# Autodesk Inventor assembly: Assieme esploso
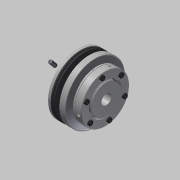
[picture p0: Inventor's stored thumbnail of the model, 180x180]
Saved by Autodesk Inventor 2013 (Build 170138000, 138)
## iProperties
Created: 2013-06
Part Number: Assieme esploso
Document SubType Name: Assembly
Designer: amir.elmekauy
Author: amir.elmekauy
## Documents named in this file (10)
- C:\Users\amir.elmekauy\Desktop\Disegni 3D\LIMITATORI\LC 170-2\Assieme chiuso.iam
- C:\Users\amir.elmekauy\Desktop\Disegni 3D\LIMITATORI\LC 170-2\Anello frizione.ipt
- C:\Users\amir.elmekauy\Desktop\Disegni 3D\LIMITATORI\LC 170-2\Bussola guida.ipt
- C:\Users\amir.elmekauy\Desktop\Disegni 3D\LIMITATORI\LC 170-2\DIN 912 - M8 x 16.ipt
- C:\Users\amir.elmekauy\Desktop\Disegni 3D\LIMITATORI\LC 170-2\Ghiera di serraggio.ipt
- C:\Users\amir.elmekauy\Desktop\Disegni 3D\LIMITATORI\LC 170-2\Molla.ipt
- C:\Users\amir.elmekauy\Desktop\Disegni 3D\LIMITATORI\LC 170-2\Mozzo.ipt
- C:\Users\amir.elmekauy\Desktop\Disegni 3D\LIMITATORI\LC 170-2\Rondella ad asola.ipt
- C:\Users\amir.elmekauy\Desktop\Disegni 3D\LIMITATORI\LC 170-2\Rondella di spinta.ipt
- C:\Users\amir.elmekauy\Desktop\Disegni 3D\LIMITATORI\LC 170-2\Grano - M10 x 25.ipt
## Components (16 placed, 9 different names)
1. Anello frizione:1 — Coincidente:1, Coincidente:18
2. Bussola guida:1 — Coincidente:3, Coincidente:19, Coincidente:20
3. DIN 912 - sostituito da DIN EN ISO 4762 M8 x 16:1 — Coincidente:12, Coincidente:21
4. Ghiera di serraggio:1 — Coincidente:4, Coincidente:12, Coincidente:13, Coincidente:14, Coincidente:15, Coincidente:16, Coincidente:17
5. Molla:1 — Coincidente:5
6. Mozzo:1 — Coincidente:6, Coincidente:9, Coincidente:11, Coincidente:18, Coincidente:19, Coincidente:27, Coincidente:28
7. Rondella ad asola:1 — Coincidente:7, Coincidente:9, Coincidente:20
8. Rondella di spinta:1 — Coincidente:10, Coincidente:11, Coincidente:21, Coincidente:22, Coincidente:23, Coincidente:24, Coincidente:25, Coincidente:26
9. Anello frizione:2 — Coincidente:2
10. DIN 912 - sostituito da DIN EN ISO 4762 M8 x 16:2 — Coincidente:13, Coincidente:22
11. DIN 912 - sostituito da DIN EN ISO 4762 M8 x 16:3 — Coincidente:16, Coincidente:26
12. DIN 912 - sostituito da DIN EN ISO 4762 M8 x 16:4 — Coincidente:17, Coincidente:25
13. DIN 912 - sostituito da DIN EN ISO 4762 M8 x 16:5 — Coincidente:15, Coincidente:24
14. DIN 912 - sostituito da DIN EN ISO 4762 M8 x 16:6 — Coincidente:14, Coincidente:23
15. DIN 913 M10 x 25:1 — Coincidente:27
16. DIN 913 M10 x 25:2 — Coincidente:28
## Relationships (27: Mate 27)
- Coincidente:1 [Mate]: Anello frizione:1
- Coincidente:2 [Mate]: Anello frizione:2
- Coincidente:3 [Mate]: Bussola guida:1
- Coincidente:4 [Mate]: Ghiera di serraggio:1
- Coincidente:5 [Mate]: Molla:1
- Coincidente:6 [Mate]: Mozzo:1
- Coincidente:7 [Mate]: Rondella ad asola:1
- Coincidente:9 [Mate]: Mozzo:1 ↔ Rondella ad asola:1
- Coincidente:10 [Mate]: Rondella di spinta:1
- Coincidente:11 [Mate]: Mozzo:1 ↔ Rondella di spinta:1
- Coincidente:12 [Mate]: DIN 912 - sostituito da DIN EN ISO 4762 M8 x 16:1 ↔ Ghiera di serraggio:1
- Coincidente:13 [Mate]: Ghiera di serraggio:1 ↔ DIN 912 - sostituito da DIN EN ISO 4762 M8 x 16:2
- Coincidente:14 [Mate]: Ghiera di serraggio:1 ↔ DIN 912 - sostituito da DIN EN ISO 4762 M8 x 16:6
- Coincidente:15 [Mate]: Ghiera di serraggio:1 ↔ DIN 912 - sostituito da DIN EN ISO 4762 M8 x 16:5
- Coincidente:16 [Mate]: Ghiera di serraggio:1 ↔ DIN 912 - sostituito da DIN EN ISO 4762 M8 x 16:3
- Coincidente:17 [Mate]: Ghiera di serraggio:1 ↔ DIN 912 - sostituito da DIN EN ISO 4762 M8 x 16:4
- Coincidente:18 [Mate]: Anello frizione:1 ↔ Mozzo:1
- Coincidente:19 [Mate]: Bussola guida:1 ↔ Mozzo:1
- Coincidente:20 [Mate]: Bussola guida:1 ↔ Rondella ad asola:1
- Coincidente:21 [Mate]: DIN 912 - sostituito da DIN EN ISO 4762 M8 x 16:1 ↔ Rondella di spinta:1
- Coincidente:22 [Mate]: Rondella di spinta:1 ↔ DIN 912 - sostituito da DIN EN ISO 4762 M8 x 16:2
- Coincidente:23 [Mate]: Rondella di spinta:1 ↔ DIN 912 - sostituito da DIN EN ISO 4762 M8 x 16:6
- Coincidente:24 [Mate]: Rondella di spinta:1 ↔ DIN 912 - sostituito da DIN EN ISO 4762 M8 x 16:5
- Coincidente:25 [Mate]: Rondella di spinta:1 ↔ DIN 912 - sostituito da DIN EN ISO 4762 M8 x 16:4
- Coincidente:26 [Mate]: Rondella di spinta:1 ↔ DIN 912 - sostituito da DIN EN ISO 4762 M8 x 16:3
- Coincidente:27 [Mate]: Mozzo:1 ↔ DIN 913 M10 x 25:1
- Coincidente:28 [Mate]: Mozzo:1 ↔ DIN 913 M10 x 25:2
